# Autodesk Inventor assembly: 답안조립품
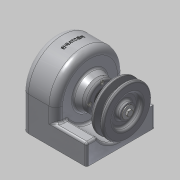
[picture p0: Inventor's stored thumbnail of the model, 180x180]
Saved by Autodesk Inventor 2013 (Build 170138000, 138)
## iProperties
Created: 2015-02
Part Number: 답안조립품
Document SubType Name: Assembly
Designer: Administrator
Author: Administrator
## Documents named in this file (14)
- C:\Users\Administrator\Desktop\450216V1018\답안조립품.iam
- C:\Users\Administrator\Desktop\450216V1018\1. 본체.ipt
- C:\Users\Administrator\Desktop\450216V1018\베어링 6001.ipt
- C:\Users\Administrator\Desktop\450216V1018\오일실.ipt
- C:\Users\Administrator\Desktop\450216V1018\축커버.ipt
- C:\Users\Administrator\Desktop\450216V1018\5. 스퍼기어.ipt
- C:\Users\Administrator\Desktop\450216V1018\축.ipt
- C:\Users\Administrator\Desktop\450216V1018\키5x5.ipt
- C:\Users\Administrator\Desktop\450216V1018\M3x0.5.ipt
- C:\Users\Administrator\Desktop\450216V1018\4. V-벨트풀리.ipt
- C:\Users\Administrator\Desktop\450216V1018\M5x0.8.ipt
- M5x0.8.ipt
- C:\Users\Administrator\Desktop\450216V1018\와샤.ipt
- C:\Users\Administrator\Desktop\450216V1018\키4x4.ipt
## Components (7 placed, 4 different names)
1. 1. 본체:1
2. 4. V-벨트풀리:1 — 플러쉬:1, 각도:1
3. M5x0.8:1 — 각도:1
4. M3x0.5:1
5. M3x0.5:2
6. M3x0.5:3
7. M3x0.5:4
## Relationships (2: Flush 1, Angle 1)
- 플러쉬:1 [Flush]: 4. V-벨트풀리:1
- 각도:1 [Angle]: 4. V-벨트풀리:1 ↔ M5x0.8:1
